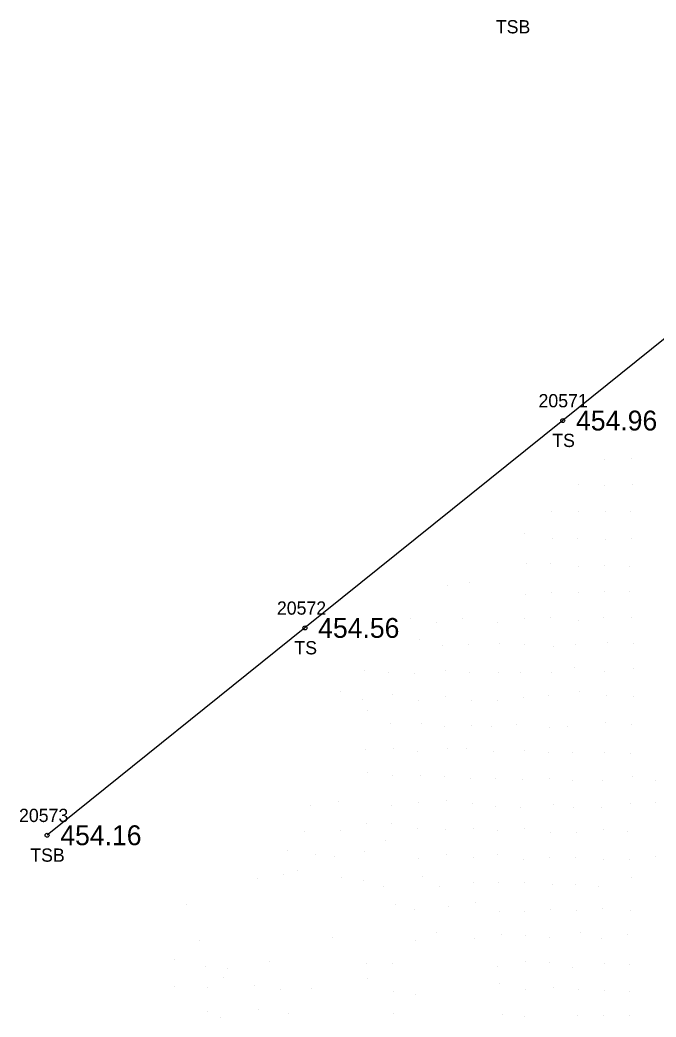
# Model space of a CAD drawing. Extents: x 1747760 to 1751131, y 649333 to 653784.
# Drawn here: x 1749009.3 to 1749057.3, y 651400.7 to 651476 of the extents above; entities that cross this region are included whole.
import ezdxf

# ---------------------------------------------------------------- set-up
doc = ezdxf.new("R2010")
doc.units = 0
for name, color, linetype in [('RD_DTM_BkLn2', 7, 'Continuous'), ('RD_DTM_BkLn_txCode', 7, 'Continuous'), ('RD_DTM_Spot', 7, 'Continuous'), ('RD_EX_TX_Misc_ELEV', 7, 'Continuous'), ('RD_SMD_Locator', 7, 'Continuous')]:
    doc.layers.add(name, color=color, linetype=linetype)

msp = doc.modelspace()

# ---------------------------------------------------------------- linework, layer by layer
at = {"layer": 'RD_DTM_BkLn2'}
msp.add_lwpolyline([(1749072.449, 651463.568), (1749050.274, 651445.743), (1749030.789, 651430.079), (1749011.304, 651414.416)], dxfattribs=at)
at = {"layer": 'RD_DTM_Spot'}
for p, q in [((1749055.456, 651444.886), (1749055.456, 651444.886)), ((1749053.431, 651442.816), (1749053.431, 651442.816)), ((1749055.43, 651442.85), (1749055.43, 651442.85)), ((1749051.479, 651440.916), (1749051.479, 651440.916)), ((1749053.448, 651440.802), (1749053.448, 651440.802)), ((1749055.555, 651440.893), (1749055.555, 651440.893)), ((1749049.395, 651438.908), (1749049.395, 651438.908)), ((1749051.491, 651438.851), (1749051.491, 651438.851)), ((1749053.52, 651438.875), (1749053.52, 651438.875)), ((1749055.416, 651438.845), (1749055.416, 651438.845)), ((1749047.368, 651437.197), (1749047.368, 651437.197)), ((1749049.466, 651436.797), (1749049.466, 651436.797)), ((1749051.422, 651436.835), (1749051.422, 651436.835)), ((1749053.515, 651436.759), (1749053.515, 651436.759)), ((1749055.451, 651436.825), (1749055.451, 651436.825)), ((1749047.5, 651434.912), (1749047.5, 651434.912)), ((1749049.377, 651434.924), (1749049.377, 651434.924)), ((1749051.493, 651434.745), (1749051.493, 651434.745)), ((1749053.434, 651434.79), (1749053.434, 651434.79)), ((1749055.308, 651434.752), (1749055.308, 651434.752)), ((1749041.531, 651433.282), (1749041.531, 651433.282)), ((1749043.191, 651433.505), (1749043.191, 651433.505)), ((1749047.473, 651432.633), (1749047.473, 651432.633)), ((1749049.387, 651432.736), (1749049.387, 651432.736)), ((1749051.489, 651432.772), (1749051.489, 651432.772)), ((1749053.436, 651432.824), (1749053.436, 651432.824)), ((1749055.3, 651432.794), (1749055.3, 651432.794)), ((1749038.762, 651430.763), (1749038.762, 651430.763)), ((1749040.733, 651430.501), (1749040.733, 651430.501)), ((1749042.7, 651430.795), (1749042.7, 651430.795)), ((1749045.321, 651430.479), (1749045.321, 651430.479)), ((1749047.352, 651430.766), (1749047.352, 651430.766)), ((1749049.379, 651430.85), (1749049.379, 651430.85)), ((1749051.484, 651430.674), (1749051.484, 651430.674)), ((1749053.37, 651430.886), (1749053.37, 651430.886)), ((1749055.489, 651430.877), (1749055.489, 651430.877)), ((1749039.478, 651429.19), (1749039.478, 651429.19)), ((1749041.198, 651428.779), (1749041.198, 651428.779)), ((1749043.123, 651428.8), (1749043.123, 651428.8)), ((1749045.462, 651428.868), (1749045.462, 651428.868)), ((1749047.384, 651428.853), (1749047.384, 651428.853)), ((1749051.243, 651428.794), (1749051.243, 651428.794)), ((1749053.62, 651428.965), (1749053.62, 651428.965)), ((1749055.59, 651428.923), (1749055.59, 651428.923)), ((1749049.575, 651428.681), (1749049.575, 651428.681)), ((1749035.314, 651426.887), (1749035.314, 651426.887)), ((1749037.072, 651426.683), (1749037.072, 651426.683)), ((1749039.058, 651426.628), (1749039.058, 651426.628)), ((1749041.387, 651426.89), (1749041.387, 651426.89)), ((1749043.21, 651426.721), (1749043.21, 651426.721)), ((1749045.388, 651426.747), (1749045.388, 651426.747)), ((1749047.113, 651426.702), (1749047.113, 651426.702)), ((1749049.412, 651426.747), (1749049.412, 651426.747)), ((1749051.167, 651427.089), (1749051.167, 651427.089)), ((1749053.404, 651426.789), (1749053.404, 651426.789)), ((1749055.584, 651427.008), (1749055.584, 651427.008)), ((1749033.474, 651425.26), (1749033.474, 651425.26)), ((1749037.376, 651425.015), (1749037.376, 651425.015)), ((1749049.184, 651424.956), (1749049.184, 651424.956)), ((1749051.549, 651425.263), (1749051.549, 651425.263)), ((1749053.566, 651424.95), (1749053.566, 651424.95)), ((1749035.111, 651424.656), (1749035.111, 651424.656)), ((1749039.337, 651424.63), (1749039.337, 651424.63)), ((1749041.408, 651424.883), (1749041.408, 651424.883)), ((1749043.397, 651424.593), (1749043.397, 651424.593)), ((1749045.315, 651424.587), (1749045.315, 651424.587)), ((1749047.296, 651424.794), (1749047.296, 651424.794)), ((1749055.596, 651424.88), (1749055.596, 651424.88)), ((1749035.49, 651423.849), (1749035.49, 651423.849)), ((1749037.232, 651422.868), (1749037.232, 651422.868)), ((1749039.577, 651422.831), (1749039.577, 651422.831)), ((1749043.36, 651422.685), (1749043.36, 651422.685)), ((1749046.751, 651422.762), (1749046.751, 651422.762)), ((1749053.491, 651422.91), (1749053.491, 651422.91)), ((1749055.428, 651422.751), (1749055.428, 651422.751)), ((1749041.318, 651422.596), (1749041.318, 651422.596)), ((1749044.893, 651422.639), (1749044.893, 651422.639)), ((1749049.232, 651422.582), (1749049.232, 651422.582)), ((1749050.599, 651422.603), (1749050.599, 651422.603)), ((1749035.401, 651420.932), (1749035.401, 651420.932)), ((1749037.449, 651420.941), (1749037.449, 651420.941)), ((1749039.332, 651420.73), (1749039.332, 651420.73)), ((1749041.57, 651420.935), (1749041.57, 651420.935)), ((1749043.028, 651420.995), (1749043.028, 651420.995)), ((1749045.061, 651420.758), (1749045.061, 651420.758)), ((1749047.364, 651420.804), (1749047.364, 651420.804)), ((1749049.186, 651420.636), (1749049.186, 651420.636)), ((1749051.006, 651420.659), (1749051.006, 651420.659)), ((1749053.452, 651420.642), (1749053.452, 651420.642)), ((1749055.425, 651420.608), (1749055.425, 651420.608)), ((1749035.488, 651419.158), (1749035.488, 651419.158)), ((1749037.425, 651418.92), (1749037.425, 651418.92)), ((1749039.493, 651418.965), (1749039.493, 651418.965)), ((1749041.323, 651418.846), (1749041.323, 651418.846)), ((1749043.332, 651418.74), (1749043.332, 651418.74)), ((1749045.223, 651418.735), (1749045.223, 651418.735)), ((1749047.229, 651418.635), (1749047.229, 651418.635)), ((1749049.289, 651418.714), (1749049.289, 651418.714)), ((1749051.017, 651418.519), (1749051.017, 651418.519)), ((1749053.253, 651418.568), (1749053.253, 651418.568)), ((1749055.549, 651418.824), (1749055.549, 651418.824)), ((1749057.25, 651418.583), (1749057.25, 651418.583)), ((1749031.224, 651416.674), (1749031.224, 651416.674)), ((1749033.328, 651416.938), (1749033.328, 651416.938)), ((1749037.347, 651416.696), (1749037.347, 651416.696)), ((1749039.349, 651416.875), (1749039.349, 651416.875)), ((1749041.451, 651417.034), (1749041.451, 651417.034)), ((1749043.449, 651416.796), (1749043.449, 651416.796)), ((1749049.546, 651416.76), (1749049.546, 651416.76)), ((1749055.378, 651416.793), (1749055.378, 651416.793)), ((1749057.262, 651416.856), (1749057.262, 651416.856)), ((1749045.188, 651416.583), (1749045.188, 651416.583)), ((1749047.058, 651416.501), (1749047.058, 651416.501)), ((1749051.078, 651416.531), (1749051.078, 651416.531)), ((1749053.204, 651416.542), (1749053.204, 651416.542)), ((1749035.47, 651415.289), (1749035.47, 651415.289)), ((1749037.306, 651415.324), (1749037.306, 651415.324)), ((1749030.791, 651414.688), (1749030.791, 651414.688)), ((1749033.439, 651414.809), (1749033.439, 651414.809)), ((1749039.275, 651414.962), (1749039.275, 651414.962)), ((1749041.433, 651414.851), (1749041.433, 651414.851)), ((1749043.562, 651414.894), (1749043.562, 651414.894)), ((1749045.324, 651414.795), (1749045.324, 651414.795)), ((1749047.364, 651414.911), (1749047.364, 651414.911)), ((1749049.312, 651414.601), (1749049.312, 651414.601)), ((1749051.307, 651414.613), (1749051.307, 651414.613)), ((1749053.319, 651414.816), (1749053.319, 651414.816)), ((1749055.189, 651414.704), (1749055.189, 651414.704)), ((1749036.841, 651414.026), (1749036.841, 651414.026)), ((1749029.439, 651413.238), (1749029.439, 651413.238)), ((1749031.62, 651412.944), (1749031.62, 651412.944)), ((1749035.282, 651413.194), (1749035.282, 651413.194)), ((1749041.472, 651412.947), (1749041.472, 651412.947)), ((1749045.33, 651412.973), (1749045.33, 651412.973)), ((1749032.987, 651412.811), (1749032.987, 651412.811)), ((1749039.355, 651412.689), (1749039.355, 651412.689)), ((1749043.508, 651412.719), (1749043.508, 651412.719)), ((1749047.307, 651412.617), (1749047.307, 651412.617)), ((1749049.26, 651412.718), (1749049.26, 651412.718)), ((1749051.214, 651412.771), (1749051.214, 651412.771)), ((1749053.316, 651412.592), (1749053.316, 651412.592)), ((1749055.304, 651412.617), (1749055.304, 651412.617)), ((1749057.255, 651412.794), (1749057.255, 651412.794)), ((1749029.204, 651411.471), (1749029.204, 651411.471)), ((1749030.235, 651411.72), (1749030.235, 651411.72)), ((1749027.18, 651411.144), (1749027.18, 651411.144)), ((1749033.564, 651411.237), (1749033.564, 651411.237)), ((1749035.245, 651410.97), (1749035.245, 651410.97)), ((1749039.644, 651411.327), (1749039.644, 651411.327)), ((1749043.553, 651410.834), (1749043.553, 651410.834)), ((1749045.448, 651410.821), (1749045.448, 651410.821)), ((1749047.399, 651410.833), (1749047.399, 651410.833)), ((1749049.481, 651410.71), (1749049.481, 651410.71)), ((1749051.263, 651410.724), (1749051.263, 651410.724)), ((1749055.458, 651411.223), (1749055.458, 651411.223)), ((1749036.735, 651410.521), (1749036.735, 651410.521)), ((1749040.967, 651410.538), (1749040.967, 651410.538)), ((1749052.963, 651410.516), (1749052.963, 651410.516)), ((1749021.844, 651409.154), (1749021.844, 651409.154)), ((1749037.66, 651409.218), (1749037.66, 651409.218)), ((1749043.649, 651409.32), (1749043.649, 651409.32)), ((1749039.085, 651408.81), (1749039.085, 651408.81)), ((1749041.609, 651409.009), (1749041.609, 651409.009)), ((1749045.468, 651408.679), (1749045.468, 651408.679)), ((1749047.373, 651408.635), (1749047.373, 651408.635)), ((1749049.341, 651408.841), (1749049.341, 651408.841)), ((1749051.346, 651408.708), (1749051.346, 651408.708)), ((1749053.275, 651408.87), (1749053.275, 651408.87)), ((1749055.358, 651408.696), (1749055.358, 651408.696)), ((1749040.705, 651407.085), (1749040.705, 651407.085)), ((1749045.626, 651406.946), (1749045.626, 651406.946)), ((1749051.616, 651407.071), (1749051.616, 651407.071)), ((1749055.185, 651406.887), (1749055.185, 651406.887)), ((1749022.848, 651406.493), (1749022.848, 651406.493)), ((1749032.894, 651406.717), (1749032.894, 651406.717)), ((1749039.161, 651406.478), (1749039.161, 651406.478)), ((1749043.601, 651406.649), (1749043.601, 651406.649)), ((1749047.469, 651406.81), (1749047.469, 651406.81)), ((1749049.232, 651406.694), (1749049.232, 651406.694)), ((1749053.206, 651406.607), (1749053.206, 651406.607)), ((1749020.932, 651405.05), (1749020.932, 651405.05)), ((1749028.08, 651404.897), (1749028.08, 651404.897)), ((1749035.432, 651404.716), (1749035.432, 651404.716)), ((1749037.427, 651404.71), (1749037.427, 651404.71)), ((1749047.456, 651404.845), (1749047.456, 651404.845)), ((1749049.24, 651404.816), (1749049.24, 651404.816)), ((1749053.4, 651404.733), (1749053.4, 651404.733)), ((1749055.289, 651404.684), (1749055.289, 651404.684)), ((1749023.275, 651404.469), (1749023.275, 651404.469)), ((1749024.925, 651404.328), (1749024.925, 651404.328)), ((1749045.349, 651404.497), (1749045.349, 651404.497)), ((1749050.972, 651404.464), (1749050.972, 651404.464)), ((1749024.641, 651403.651), (1749024.641, 651403.651)), ((1749035.486, 651403.584), (1749035.486, 651403.584)), ((1749045.476, 651403.235), (1749045.476, 651403.235)), ((1749020.96, 651402.96), (1749020.96, 651402.96)), ((1749023.397, 651402.936), (1749023.397, 651402.936)), ((1749026.945, 651403.071), (1749026.945, 651403.071)), ((1749028.95, 651402.741), (1749028.95, 651402.741)), ((1749031.313, 651402.825), (1749031.313, 651402.825)), ((1749037.454, 651402.648), (1749037.454, 651402.648)), ((1749039.136, 651402.412), (1749039.136, 651402.412)), ((1749047.491, 651402.772), (1749047.491, 651402.772)), ((1749049.558, 651402.949), (1749049.558, 651402.949)), ((1749051.463, 651402.77), (1749051.463, 651402.77)), ((1749053.394, 651402.725), (1749053.394, 651402.725)), ((1749055.299, 651402.647), (1749055.299, 651402.647)), ((1749023.447, 651401.115), (1749023.447, 651401.115)), ((1749027.275, 651401.259), (1749027.275, 651401.259)), ((1749029.547, 651400.944), (1749029.547, 651400.944)), ((1749037.477, 651400.938), (1749037.477, 651400.938)), ((1749045.697, 651400.88), (1749045.697, 651400.88)), ((1749024.41, 651400.683), (1749024.41, 651400.683)), ((1749047.364, 651400.691), (1749047.364, 651400.691)), ((1749051.347, 651400.774), (1749051.347, 651400.774)), ((1749053.336, 651400.809), (1749053.336, 651400.809)), ((1749055.345, 651400.763), (1749055.345, 651400.763))]:
    msp.add_line(p, q, dxfattribs=at)
at = {"layer": 'RD_SMD_Locator'}
for centre in [(1749050.274, 651445.743), (1749030.789, 651430.079), (1749011.304, 651414.416)]:
    msp.add_circle(centre, 0.15, dxfattribs=at)

# ---------------------------------------------------------------- texts
at = {"layer": 'RD_DTM_BkLn_txCode'}
for s, p in [('TSB', (1749045.215, 651474.991)), ('20571', (1749048.439, 651446.743)), ('TS', (1749049.479, 651443.743)), ('20572', (1749028.671, 651431.079)), ('TS', (1749029.994, 651428.079)), ('20573', (1749009.186, 651415.416)), ('TSB', (1749010.036, 651412.416))]:
    msp.add_text(s, height=1, dxfattribs=at).set_placement(p)
at = {"layer": 'RD_EX_TX_Misc_ELEV'}
for s, p in [('454.96', (1749051.274, 651444.993)), ('454.56', (1749031.789, 651429.329)), ('454.16', (1749012.304, 651413.666))]:
    msp.add_text(s, height=1.5, dxfattribs=at).set_placement(p)

doc.saveas('drawing.dxf')
